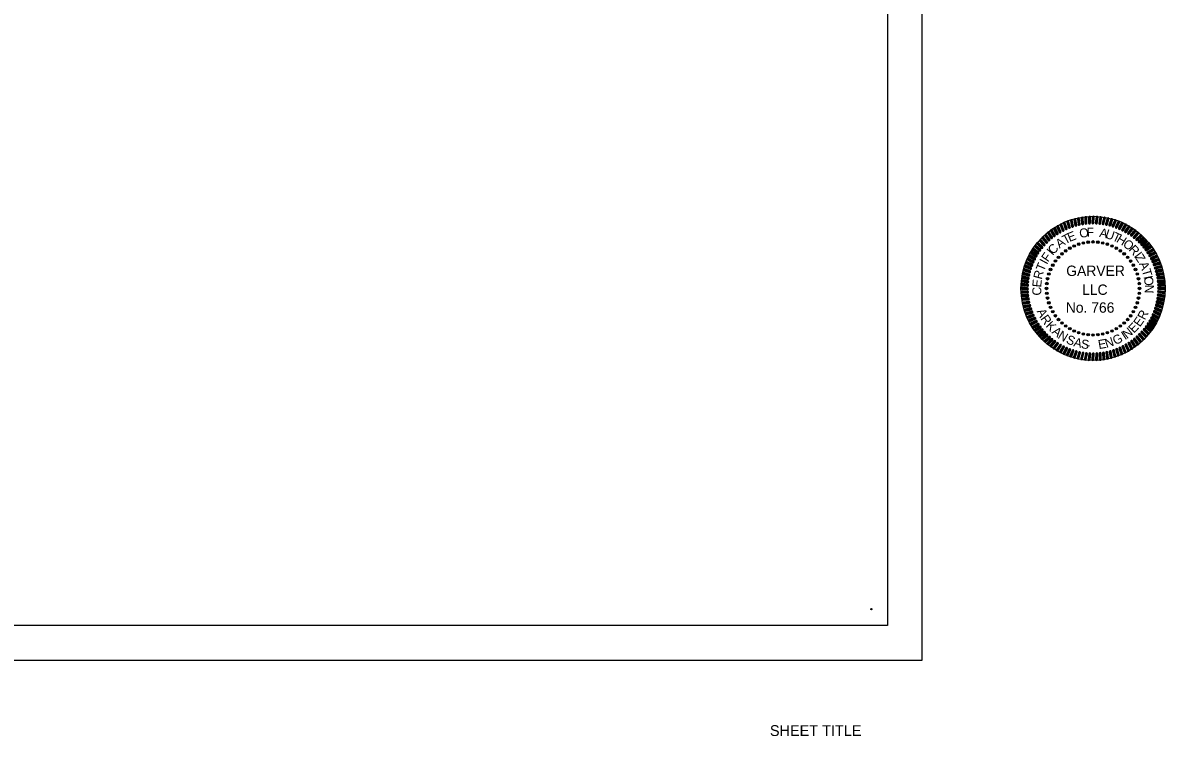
# Model space of a CAD drawing. Extents: x 0 to 19, y -0.6 to 11.2.
# Drawn here: x 9.51 to 19.02, y -0.63 to 5.3 of the extents above; entities that cross this region are included whole.
import ezdxf

# ---------------------------------------------------------------- set-up
doc = ezdxf.new("R2010")
doc.units = 0
for name, color, linetype in [('G-ANNO-STMP', 7, 'Continuous'), ('G-ANNO-TEXT', 7, 'Continuous'), ('G-Border-Paper', 7, 'Continuous'), ('G-Border-Sheet', 7, 'Continuous'), ('G-No Plot-Anchor', 7, 'Continuous'), ('G-No Plot-Stamp-1', 7, 'Continuous'), ('G-No Plot-Stamp-2', 7, 'Continuous')]:
    doc.layers.add(name, color=color, linetype=linetype)

# ---------------------------------------------------------------- blocks, each defined once
blk = doc.blocks.new('SEALDO')
at = {"layer": 'G-ANNO-TEXT'}
for radius in [0.0396, 0.0305, 0.0213, 0.0122, 0.00305]:
    blk.add_circle((1.403, -0.456), radius, dxfattribs=at)
blk = doc.blocks.new('SEALRI')
at = {"layer": 'G-ANNO-TEXT'}
for p, q in [((-0.023, 2.258), (-0.038, 2.081)), ((-0.008, 2.281), (-0.028, 2.056)), ((0.004, 2.286), (-0.016, 2.049)), ((0.016, 2.285), (-0.004, 2.048)), ((0.028, 2.278), (0.008, 2.052)), ((0.023, 2.076), (0.038, 2.253))]:
    blk.add_line(p, q, dxfattribs=at)
for centre, start, end in [((0.008, 2.256), 355, 175), ((-0.008, 2.078), 175, 355)]:
    blk.add_arc(centre, 0.0305, start, end, dxfattribs=at)

msp = doc.modelspace()

# ---------------------------------------------------------------- linework, layer by layer
at = {"layer": 'G-Border-Paper'}
msp.add_lwpolyline([(17, 11), (0, 11), (0, 0), (17, 0)], close=True, dxfattribs=at)
at = {"layer": 'G-Border-Sheet'}
msp.add_lwpolyline([(0.758, 5.5), (16.7116, 5.5), (16.7116, 0.2884), (0.758, 0.2884)], close=True, dxfattribs=at)
at = {"layer": 'G-No Plot-Anchor'}
msp.add_circle((16.5766, 0.4234), 0.005, dxfattribs=at)
at = {"layer": 'G-No Plot-Stamp-1'}
msp.add_circle((18.4222, 3.0925), 0.6, dxfattribs=at)
at = {"layer": 'G-No Plot-Stamp-2'}
msp.add_circle((18.4222, 3.0925), 0.6, dxfattribs=at)

# ---------------------------------------------------------------- block references
at = {"layer": 'G-ANNO-STMP'}
for name, xscale, yscale, rotation in [('SEALRI', 0.2624620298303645, 0.2624620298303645, 30.00000000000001), ('SEALRI', 0.2624620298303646, 0.26246202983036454, 26.99999999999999), ('SEALRI', 0.26246202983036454, 0.26246202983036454, 23.99999999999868), ('SEALRI', 0.26246202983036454, 0.26246202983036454, 20.999999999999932), ('SEALRI', 0.2624620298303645, 0.26246202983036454, 18), ('SEALRI', 0.2624620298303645, 0.2624620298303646, 15.000000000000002), ('SEALRI', 0.2624620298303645, 0.2624620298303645, 12.000000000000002), ('SEALRI', 0.2624620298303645, 0.2624620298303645, 9), ('SEALRI', 0.2624620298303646, 0.26246202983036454, 6), ('SEALRI', 0.2624620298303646, 0.2624620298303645, 3.0000000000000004), ('SEALRI', 0.26246202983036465, 0.2624620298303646, -2.9999999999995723), ('SEALRI', 0.2624620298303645, 0.2624620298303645, -5.9999999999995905), ('SEALRI', 0.2624620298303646, 0.26246202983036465, -8.999999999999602), ('SEALRI', 0.2624620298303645, 0.26246202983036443, -11.999999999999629), ('SEALRI', 0.2624620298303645, 0.2624620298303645, -14.999999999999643), ('SEALRI', 0.26246202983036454, 0.2624620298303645, -17.99999999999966), ('SEALRI', 0.2624620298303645, 0.26246202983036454, -20.999999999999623), ('SEALRI', 0.2624620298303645, 0.26246202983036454, -23.999999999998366), ('SEALRI', 0.26246202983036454, 0.26246202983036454, -26.999999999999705), ('SEALRI', 0.26246202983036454, 0.2624620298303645, -29.99999999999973), ('SEALRI', 0.26246202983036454, 0.2624620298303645, 44.999999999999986), ('SEALRI', 0.26246202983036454, 0.2624620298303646, 41.999999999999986), ('SEALRI', 0.26246202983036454, 0.26246202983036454, 38.999999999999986), ('SEALRI', 0.2624620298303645, 0.2624620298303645, 36), ('SEALRI', 0.2624620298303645, 0.26246202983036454, 33), ('SEALRI', 0.26246202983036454, 0.2624620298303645, -32.999999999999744), ('SEALRI', 0.2624620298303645, 0.2624620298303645, -35.999999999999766), ('SEALRI', 0.26246202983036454, 0.2624620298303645, -38.999999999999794), ('SEALRI', 0.26246202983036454, 0.2624620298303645, -41.99999999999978), ('SEALRI', 0.26246202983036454, 0.2624620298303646, -44.999999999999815), ('SEALRI', 0.26246202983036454, 0.2624620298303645, 56.99999999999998), ('SEALRI', 0.2624620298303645, 0.2624620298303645, 54), ('SEALRI', 0.26246202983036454, 0.26246202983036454, 50.99999999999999), ('SEALRI', 0.2624620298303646, 0.26246202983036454, 47.99999999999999), ('SEALDO', 0.26246202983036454, 0.26246202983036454, 138), ('SEALDO', 0.2624620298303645, 0.26246202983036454, 131.99999999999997), ('SEALDO', 0.2624620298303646, 0.26246202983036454, 125.99999999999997), ('SEALDO', 0.2624620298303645, 0.26246202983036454, 119.99999999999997), ('SEALDO', 0.2624620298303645, 0.26246202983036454, 113.99999999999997), ('SEALDO', 0.26246202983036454, 0.2624620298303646, 107.99999999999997), ('SEALDO', 0.26246202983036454, 0.26246202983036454, 101.99999999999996), ('SEALDO', 0.2624620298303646, 0.2624620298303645, 95.99999999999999), ('SEALDO', 0.26246202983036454, 0.26246202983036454, 90), ('SEALDO', 0.2624620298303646, 0.26246202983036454, 83.99999999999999), ('SEALDO', 0.2624620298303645, 0.26246202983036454, 77.99999999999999), ('SEALRI', 0.26246202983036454, 0.2624620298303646, -47.99999999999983), ('SEALRI', 0.2624620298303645, 0.26246202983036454, -50.999999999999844), ('SEALRI', 0.2624620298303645, 0.26246202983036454, -53.99999999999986), ('SEALRI', 0.2624620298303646, 0.26246202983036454, -56.999999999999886), ('SEALRI', 0.26246202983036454, 0.2624620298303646, 65.99999999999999), ('SEALRI', 0.26246202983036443, 0.2624620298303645, 63), ('SEALRI', 0.2624620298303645, 0.2624620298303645, 59.999999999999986), ('SEALDO', 0.2624620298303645, 0.26246202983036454, 162.00000000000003), ('SEALDO', 0.26246202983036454, 0.2624620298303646, 156.00000000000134), ('SEALDO', 0.26246202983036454, 0.2624620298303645, 150), ('SEALDO', 0.2624620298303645, 0.26246202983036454, 144), ('SEALDO', 0.2624620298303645, 0.26246202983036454, 72), ('SEALDO', 0.26246202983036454, 0.2624620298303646, 66.00000000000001), ('SEALDO', 0.26246202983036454, 0.2624620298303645, 60.00000000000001), ('SEALDO', 0.2624620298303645, 0.2624620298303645, 54), ('SEALRI', 0.2624620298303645, 0.26246202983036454, -59.99999999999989), ('SEALRI', 0.2624620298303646, 0.26246202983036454, -62.99999999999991), ('SEALRI', 0.26246202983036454, 0.2624620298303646, -65.99999999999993), ('SEALRI', 0.2624620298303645, 0.26246202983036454, 75.00000000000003), ('SEALRI', 0.2624620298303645, 0.26246202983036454, 72), ('SEALRI', 0.26246202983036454, 0.2624620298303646, 68.99999999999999), ('SEALDO', 0.2624620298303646, 0.2624620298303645, 174.00000000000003), ('SEALDO', 0.26246202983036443, 0.2624620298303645, 168.00000000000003), ('SEALDO', 0.26246202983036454, 0.2624620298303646, 48.00000000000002), ('SEALDO', 0.2624620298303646, 0.26246202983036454, 42.000000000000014), ('SEALRI', 0.26246202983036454, 0.26246202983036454, -68.99999999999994), ('SEALRI', 0.26246202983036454, 0.26246202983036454, -71.99999999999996), ('SEALRI', 0.26246202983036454, 0.2624620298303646, -74.99999999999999), ('SEALRI', 0.2624620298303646, 0.26246202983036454, 84.00000000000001), ('SEALRI', 0.2624620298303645, 0.2624620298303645, 81), ('SEALRI', 0.2624620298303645, 0.2624620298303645, 78.00000000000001), ('SEALDO', 0.2624620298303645, 0.26246202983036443, -167.99999999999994), ('SEALDO', 0.26246202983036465, 0.26246202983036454, -173.99999999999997), ('SEALDO', 0.26246202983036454, 0.26246202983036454, -179.99999999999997), ('SEALDO', 0.2624620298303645, 0.2624620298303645, 36), ('SEALDO', 0.26246202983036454, 0.2624620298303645, 29.999999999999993), ('SEALDO', 0.26246202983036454, 0.26246202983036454, 23.99999999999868), ('SEALRI', 0.2624620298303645, 0.2624620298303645, -78), ('SEALRI', 0.2624620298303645, 0.2624620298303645, -81.00000000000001), ('SEALRI', 0.2624620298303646, 0.2624620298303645, -84.00000000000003), ('SEALRI', 0.26246202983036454, 0.26246202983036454, 90.00000000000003), ('SEALRI', 0.26246202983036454, 0.26246202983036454, 87.00000000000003), ('SEALRI', 0.2624620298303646, 0.2624620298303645, 93), ('SEALRI', 0.2624620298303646, 0.26246202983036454, 96.00000000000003), ('SEALDO', 0.2624620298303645, 0.26246202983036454, -161.99999999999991), ('SEALDO', 0.2624620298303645, 0.26246202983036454, -156.00000000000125), ('SEALDO', 0.2624620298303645, 0.2624620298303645, 12.000000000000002), ('SEALDO', 0.2624620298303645, 0.26246202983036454, 18), ('SEALRI', 0.26246202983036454, 0.2624620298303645, -96.0000000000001), ('SEALRI', 0.26246202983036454, 0.26246202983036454, -87.00000000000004), ('SEALRI', 0.2624620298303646, 0.26246202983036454, -93.00000000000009), ('SEALRI', 0.26246202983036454, 0.26246202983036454, -90.00000000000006), ('SEALRI', 0.26246202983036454, 0.26246202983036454, 99.00000000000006), ('SEALRI', 0.2624620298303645, 0.2624620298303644, 102.00000000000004), ('SEALRI', 0.26246202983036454, 0.2624620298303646, 105.00000000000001), ('SEALDO', 0.26246202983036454, 0.26246202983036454, -149.99999999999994), ('SEALDO', 0.2624620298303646, 0.26246202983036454, -143.99999999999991), ('SEALDO', 0.26246202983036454, 0.2624620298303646, -137.9999999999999), ('SEALDO', 0.2624620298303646, 0.26246202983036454, 6), ('SEALRI', 0.26246202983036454, 0.2624620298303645, -105.00000000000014), ('SEALRI', 0.2624620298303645, 0.2624620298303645, -102.00000000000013), ('SEALRI', 0.26246202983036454, 0.2624620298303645, -99.00000000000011), ('SEALRI', 0.26246202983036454, 0.26246202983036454, 108.00000000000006), ('SEALRI', 0.2624620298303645, 0.2624620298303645, 111.00000000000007), ('SEALRI', 0.26246202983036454, 0.26246202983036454, 114.00000000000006), ('SEALRI', 0.26246202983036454, 0.26246202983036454, 117.00000000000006), ('SEALDO', 0.26246202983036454, 0.26246202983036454, -131.99999999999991), ('SEALDO', 0.26246202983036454, 0.2624620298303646, -125.9999999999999), ('SEALDO', 0.2624620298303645, 0.26246202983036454, -18.000000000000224), ('SEALDO', 0.2624620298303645, 0.26246202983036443, -12.000000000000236), ('SEALDO', 0.26246202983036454, 0.2624620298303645, -6.000000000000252), ('SEALRI', 0.26246202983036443, 0.2624620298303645, -117.00000000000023), ('SEALRI', 0.26246202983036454, 0.2624620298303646, -114.0000000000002), ('SEALRI', 0.26246202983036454, 0.26246202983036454, -111.00000000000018), ('SEALRI', 0.26246202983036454, 0.2624620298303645, -108.00000000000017), ('SEALRI', 0.2624620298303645, 0.2624620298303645, 120.00000000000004), ('SEALRI', 0.2624620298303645, 0.2624620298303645, 123.00000000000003), ('SEALRI', 0.26246202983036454, 0.26246202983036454, 126.00000000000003), ('SEALRI', 0.26246202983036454, 0.26246202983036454, 129.00000000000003), ('SEALDO', 0.2624620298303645, 0.26246202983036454, -119.99999999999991), ('SEALDO', 0.26246202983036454, 0.26246202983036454, -113.99999999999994), ('SEALDO', 0.26246202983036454, 0.26246202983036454, -107.99999999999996), ('SEALDO', 0.2624620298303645, 0.26246202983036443, -101.99999999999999), ('SEALDO', 0.2624620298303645, 0.2624620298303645, -42.00000000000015), ('SEALDO', 0.2624620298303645, 0.2624620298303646, -36.00000000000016), ('SEALDO', 0.2624620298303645, 0.26246202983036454, -30.00000000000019), ('SEALDO', 0.26246202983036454, 0.2624620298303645, -23.999999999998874), ('SEALRI', 0.2624620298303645, 0.26246202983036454, -129.00000000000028), ('SEALRI', 0.26246202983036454, 0.2624620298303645, -126.00000000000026), ('SEALRI', 0.2624620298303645, 0.26246202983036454, -123.00000000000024), ('SEALRI', 0.26246202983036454, 0.2624620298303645, -120.00000000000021), ('SEALRI', 0.26246202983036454, 0.2624620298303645, 132), ('SEALRI', 0.2624620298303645, 0.26246202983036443, 135), ('SEALRI', 0.26246202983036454, 0.26246202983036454, 138), ('SEALRI', 0.2624620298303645, 0.26246202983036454, 140.99999999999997), ('SEALRI', 0.2624620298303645, 0.26246202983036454, 144), ('SEALDO', 0.2624620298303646, 0.26246202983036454, -96), ('SEALDO', 0.26246202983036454, 0.26246202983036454, -90.00000000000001), ('SEALDO', 0.2624620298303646, 0.2624620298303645, -84.00000000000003), ('SEALDO', 0.26246202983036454, 0.26246202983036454, -78.00000000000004), ('SEALDO', 0.26246202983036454, 0.2624620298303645, -72.00000000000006), ('SEALDO', 0.2624620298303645, 0.26246202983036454, -66.00000000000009), ('SEALDO', 0.26246202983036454, 0.26246202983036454, -60.0000000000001), ('SEALDO', 0.26246202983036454, 0.26246202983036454, -54.000000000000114), ('SEALDO', 0.26246202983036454, 0.26246202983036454, -48.00000000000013), ('SEALRI', 0.2624620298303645, 0.26246202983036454, -144.00000000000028), ('SEALRI', 0.26246202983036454, 0.2624620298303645, -141.0000000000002), ('SEALRI', 0.26246202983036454, 0.2624620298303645, -138.00000000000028), ('SEALRI', 0.2624620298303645, 0.2624620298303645, -135.00000000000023), ('SEALRI', 0.2624620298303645, 0.26246202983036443, -132.00000000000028), ('SEALRI', 0.2624620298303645, 0.26246202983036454, 146.99999999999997), ('SEALRI', 0.2624620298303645, 0.26246202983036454, 149.99999999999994), ('SEALRI', 0.2624620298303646, 0.26246202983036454, 152.99999999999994), ('SEALRI', 0.2624620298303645, 0.2624620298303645, 156.00000000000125), ('SEALRI', 0.2624620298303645, 0.26246202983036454, 159), ('SEALRI', 0.2624620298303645, 0.2624620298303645, 161.99999999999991), ('SEALRI', 0.2624620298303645, 0.26246202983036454, 164.99999999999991), ('SEALRI', 0.2624620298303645, 0.26246202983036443, 167.99999999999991), ('SEALRI', 0.2624620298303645, 0.2624620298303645, -168.0000000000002), ('SEALRI', 0.2624620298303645, 0.2624620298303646, -165.0000000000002), ('SEALRI', 0.2624620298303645, 0.26246202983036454, -162.00000000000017), ('SEALRI', 0.26246202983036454, 0.26246202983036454, -159.00000000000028), ('SEALRI', 0.2624620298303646, 0.2624620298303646, -156.00000000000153), ('SEALRI', 0.2624620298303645, 0.2624620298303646, -153.00000000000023), ('SEALRI', 0.2624620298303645, 0.26246202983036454, -150.00000000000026), ('SEALRI', 0.26246202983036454, 0.2624620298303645, -147.00000000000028), ('SEALRI', 0.26246202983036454, 0.2624620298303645, 170.9999999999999), ('SEALRI', 0.26246202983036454, 0.2624620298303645, 173.9999999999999), ('SEALRI', 0.2624620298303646, 0.2624620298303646, 176.9999999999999), ('SEALRI', 0.26246202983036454, 0.26246202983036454, 179.99999999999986), ('SEALRI', 0.2624620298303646, 0.26246202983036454, -177.00000000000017), ('SEALRI', 0.2624620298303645, 0.2624620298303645, -174.00000000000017), ('SEALRI', 0.26246202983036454, 0.2624620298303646, -171.00000000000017)]:
    msp.add_blockref(name, (18.4223, 3.0925), dxfattribs=dict(at, xscale=xscale, yscale=yscale, rotation=rotation))
at = {"layer": 'G-ANNO-STMP', "xscale": 0.26246202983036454, "yscale": 0.26246202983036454}
for name in ['SEALRI', 'SEALDO']:
    msp.add_blockref(name, (18.4223, 3.0925), dxfattribs=at)

# ---------------------------------------------------------------- texts
at = {"layer": 'G-ANNO-STMP'}
for s, rotation, p in [('T', 28.2771, (18.1905, 3.4573)), ('E', 21.61044, (18.2267, 3.4785)), ('O', 8.2771, (18.3136, 3.5123)), ('F', 1.61044, (18.3705, 3.522)), ('A', 348.2771, (18.4707, 3.5227)), ('U', 341.27715, (18.5176, 3.5152)), ('T', 334.94377, (18.5765, 3.4962)), ('H', 328.2771, (18.6103, 3.4828)), ('I', 49.74076, (18.0858, 3.3622)), ('C', 44.38813, (18.0896, 3.3699)), ('A', 34.94377, (18.1428, 3.4228)), ('O', 319.7874, (18.6645, 3.452)), ('R', 311.99331, (18.7137, 3.4128)), ('I', 61.61044, (18.0378, 3.2871)), ('F', 54.94377, (18.0468, 3.3073)), ('I', 307.00814, (18.7595, 3.3613)), ('Z', 301.61044, (18.7683, 3.3523)), ('R', 74.94377, (17.9951, 3.1629)), ('T', 67.43139, (18.0126, 3.2289)), ('A', 292.97516, (18.8037, 3.2978)), ('T', 286.3085, (18.8272, 3.2435)), ('E', 83.89849, (17.9897, 3.0987)), ('I', 281.61044, (18.8422, 3.1908)), ('O', 276.48226, (18.8451, 3.1881)), ('C', 91.88416, (17.993, 3.0347)), ('N', 268.2771, (18.8545, 3.1248)), ('A', 296.57465, (17.9514, 2.9025)), ('R', 304.61826, (17.981, 2.8408)), ('E', 54.73091, (18.8126, 2.7672)), ('R', 63.09594, (18.8543, 2.8247)), ('K', 313.3805, (18.0231, 2.778)), ('A', 321.25836, (18.0738, 2.7232)), ('N', 38.98211, (18.705, 2.6701)), ('E', 46.68075, (18.7629, 2.7159)), ('N', 329.10994, (18.1231, 2.6817)), ('S', 337.62936, (18.1923, 2.6396)), ('A', 345.40726, (18.2555, 2.613)), ('S', 352.80457, (18.3191, 2.5952)), ('E', 10.06947, (18.4713, 2.5871)), ('N', 17.86862, (18.5341, 2.5965)), ('G', 26.41319, (18.608, 2.6194)), ('I', 32.97899, (18.6876, 2.6612)), ('-', 0.83848, (18.3644, 2.5854))]:
    msp.add_text(s, height=0.075, rotation=rotation, dxfattribs=at).set_placement(p)
for s, p in [('GARVER', (18.1993, 3.1961)), ('LLC', (18.3314, 3.039)), ('No. 766', (18.1956, 2.8903))]:
    msp.add_text(s, height=0.0864, dxfattribs=at).set_placement(p)
at = {"layer": 'G-ANNO-TEXT'}
msp.add_text('SHEET TITLE', height=0.09, dxfattribs=at).set_placement((15.7319, -0.6318))

doc.saveas('drawing.dxf')
